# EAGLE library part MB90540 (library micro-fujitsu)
MICROCONTROLLER/MEMORY DEVICE
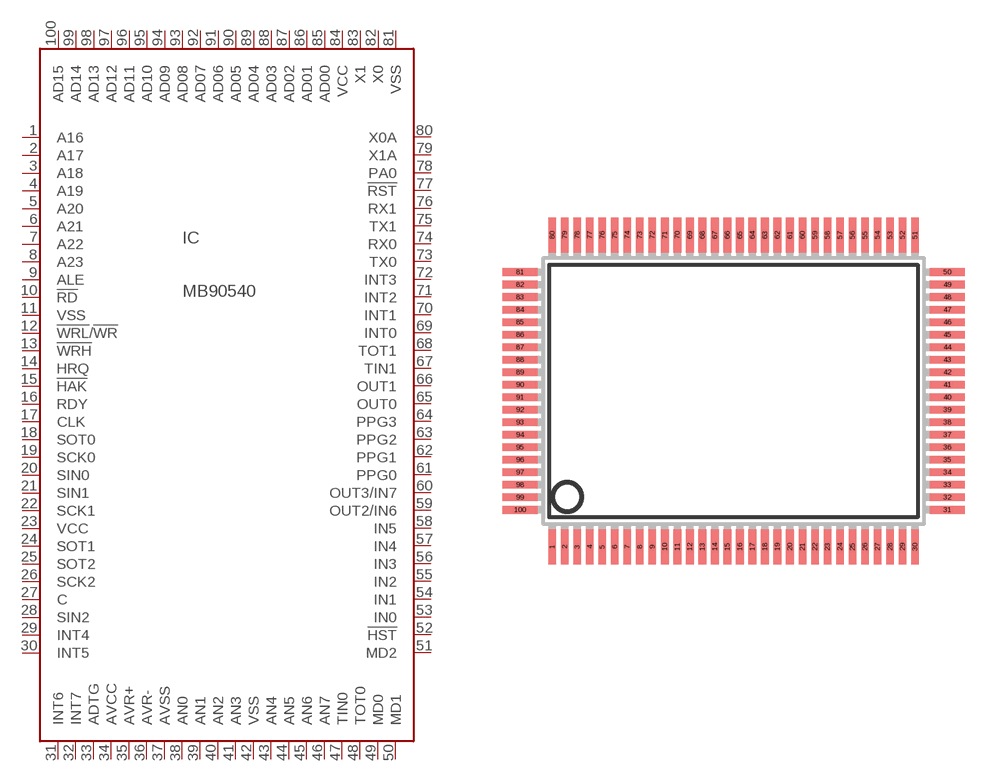
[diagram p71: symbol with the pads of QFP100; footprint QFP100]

Designator prefix IC

## MB90540 (OC_FARNELL: unknown; OC_NEWARK: unknown)  [QFP100]
1  A16
2  A17
3  A18
4  A19
5  A20
6  A21
7  A22
8  A23
9  ALE  out
10  !RD
11  VSS  pwr
12  !WRL!/!WR
13  !WRH
14  HRQ
15  !HAK
16  RDY
17  CLK
18  SOT0
19  SCK0
20  SIN0
21  SIN1
22  SCK1
23  VCC  pwr
24  SOT1
25  SOT2
26  SCK2
27  C  in
28  SIN2
29  INT4
30  INT5
31  INT6
32  INT7
33  ADTG
34  AVCC  pwr
35  AVR+  pwr
36  AVR-  pwr
37  AVSS  pwr
38  AN0
39  AN1
40  AN2
41  AN3
42  VSS  pwr
43  AN4
44  AN5
45  AN6
46  AN7
47  TIN0
48  TOT0
49  MD0  in
50  MD1  in
51  MD2  in
52  !HST  in
53  IN0
54  IN1
55  IN2
56  IN3
57  IN4
58  IN5
59  OUT2/IN6
60  OUT3/IN7
61  PPG0
62  PPG1
63  PPG2
64  PPG3
65  OUT0
66  OUT1
67  TIN1
68  TOT1
69  INT0
70  INT1
71  INT2
72  INT3
73  TX0
74  RX0
75  TX1
76  RX1
77  !RST  in
78  PA0
79  X1A  in
80  X0A  in
81  VSS  pwr
82  X0  in
83  X1  in
84  VCC  pwr
85  AD00
86  AD01
87  AD02
88  AD03
89  AD04
90  AD05
91  AD06
92  AD07
93  AD08
94  AD09
95  AD10
96  AD11
97  AD12
98  AD13
99  AD14
100  AD15

## Footprint QFP100 (pad centres in mm)
Quad Flat Pack
smd 0.4 x 1.8: 1 -9.425,-8.1; 2 -8.775,-8.1; 3 -8.125,-8.1; 4 -7.475,-8.1; 5 -6.825,-8.1; 6 -6.175,-8.1; 7 -5.525,-8.1; 8 -4.875,-8.1; 9 -4.225,-8.1; 10 -3.575,-8.1; 11 -2.925,-8.1; 12 -2.275,-8.1; 13 -1.625,-8.1; 14 -0.975,-8.1; 15 -0.325,-8.1; 16 0.325,-8.1; 17 0.975,-8.1; 18 1.625,-8.1; 19 2.275,-8.1; 20 2.925,-8.1; 21 3.575,-8.1; 22 4.225,-8.1; 23 4.875,-8.1; 24 5.525,-8.1; 25 6.175,-8.1; 26 6.825,-8.1; 27 7.475,-8.1; 28 8.125,-8.1; 29 8.775,-8.1; 30 9.425,-8.1; 51 9.425,8.1; 52 8.775,8.1; 53 8.125,8.1; 54 7.475,8.1; 55 6.825,8.1; 56 6.175,8.1; 57 5.525,8.1; 58 4.875,8.1; 59 4.225,8.1; 60 3.575,8.1; 61 2.925,8.1; 62 2.275,8.1; 63 1.625,8.1; 64 0.975,8.1; 65 0.325,8.1; 66 -0.325,8.1; 67 -0.975,8.1; 68 -1.625,8.1; 69 -2.275,8.1; 70 -2.925,8.1; 71 -3.575,8.1; 72 -4.225,8.1; 73 -4.875,8.1; 74 -5.525,8.1; 75 -6.175,8.1; 76 -6.825,8.1; 77 -7.475,8.1; 78 -8.125,8.1; 79 -8.775,8.1; 80 -9.425,8.1
smd 1.8 x 0.4: 31 11.1,-6.175; 32 11.1,-5.525; 33 11.1,-4.875; 34 11.1,-4.225; 35 11.1,-3.575; 36 11.1,-2.925; 37 11.1,-2.275; 38 11.1,-1.625; 39 11.1,-0.975; 40 11.1,-0.325; 41 11.1,0.325; 42 11.1,0.975; 43 11.1,1.625; 44 11.1,2.275; 45 11.1,2.925; 46 11.1,3.575; 47 11.1,4.225; 48 11.1,4.875; 49 11.1,5.525; 50 11.1,6.175; 81 -11.1,6.175; 82 -11.1,5.525; 83 -11.1,4.875; 84 -11.1,4.225; 85 -11.1,3.575; 86 -11.1,2.925; 87 -11.1,2.275; 88 -11.1,1.625; 89 -11.1,0.975; 90 -11.1,0.325; 91 -11.1,-0.325; 92 -11.1,-0.975; 93 -11.1,-1.625; 94 -11.1,-2.275; 95 -11.1,-2.925; 96 -11.1,-3.575; 97 -11.1,-4.225; 98 -11.1,-4.875; 99 -11.1,-5.525; 100 -11.1,-6.175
